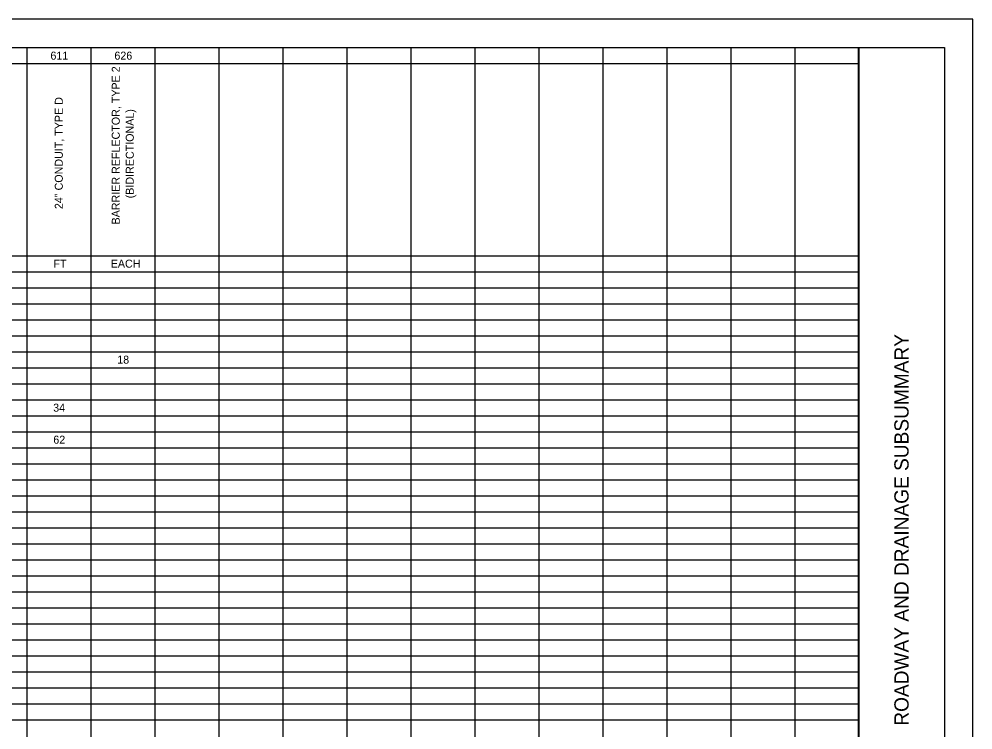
# Model space of a CAD drawing. Extents: x 0 to 34, y 0 to 22.
# Drawn here: x 17.31 to 34, y 9.56 to 22 of the extents above; entities that cross this region are included whole.
import ezdxf

# ---------------------------------------------------------------- set-up
doc = ezdxf.new("R2010")
doc.units = 0
for name, color, linetype in [('Default', 7, 'Continuous'), ('SH_Border', 7, 'Continuous'), ('SH_Cut_Line', 7, 'Continuous'), ('SH_Data', 7, 'Continuous')]:
    doc.layers.add(name, color=color, linetype=linetype)

msp = doc.modelspace()

# ---------------------------------------------------------------- linework, layer by layer
at = {"layer": 'SH_Border'}
msp.add_line((32, 0.5), (32, 21.5), dxfattribs=at)
msp.add_lwpolyline([(1.5, 21.5), (33.5, 21.5), (33.5, 0.5), (1.5, 0.5)], close=True, dxfattribs=at)
at = {"layer": 'SH_Cut_Line'}
msp.add_lwpolyline([(0, 0), (34, 0), (34, 22), (0, 22)], close=True, dxfattribs=at)
at = {"layer": 'SH_Data'}
for p, q in [((1.5, 21.5), (32.004, 21.5)), ((17.444, 21.5), (17.444, 0.5)), ((18.564, 21.5), (18.564, 0.5)), ((19.684, 21.5), (19.684, 0.5)), ((20.804, 21.5), (20.804, 0.5)), ((21.924, 21.5), (21.924, 0.5)), ((23.044, 21.5), (23.044, 0.5)), ((24.164, 21.5), (24.164, 0.5)), ((25.284, 21.5), (25.284, 0.5)), ((26.404, 21.5), (26.404, 0.5)), ((27.524, 21.5), (27.524, 0.5)), ((28.644, 21.5), (28.644, 0.5)), ((29.764, 21.5), (29.764, 0.5)), ((30.884, 21.5), (30.884, 0.5)), ((32.004, 21.5), (32.004, 0.5)), ((8.484, 21.22), (32.004, 21.22)), ((8.484, 17.86), (32.004, 17.86)), ((1.5, 17.58), (32.004, 17.58)), ((1.5, 17.3), (32.004, 17.3)), ((1.5, 17.02), (32.004, 17.02)), ((1.5, 16.74), (32.004, 16.74)), ((1.5, 16.46), (32.004, 16.46)), ((1.5, 16.18), (32.004, 16.18)), ((1.5, 15.9), (32.004, 15.9)), ((1.5, 15.62), (32.004, 15.62)), ((1.5, 15.34), (32.004, 15.34)), ((1.5, 15.06), (32.004, 15.06)), ((1.5, 14.78), (32.004, 14.78)), ((1.5, 14.5), (32.004, 14.5)), ((1.5, 14.22), (32.004, 14.22)), ((1.5, 13.94), (32.004, 13.94)), ((1.5, 13.66), (32.004, 13.66)), ((1.5, 13.38), (32.004, 13.38)), ((1.5, 13.1), (32.004, 13.1)), ((1.5, 12.82), (32.004, 12.82)), ((1.5, 12.54), (32.004, 12.54)), ((1.5, 12.26), (32.004, 12.26)), ((1.5, 11.98), (32.004, 11.98)), ((1.5, 11.7), (32.004, 11.7)), ((1.5, 11.42), (32.004, 11.42)), ((1.5, 11.14), (32.004, 11.14)), ((1.5, 10.86), (32.004, 10.86)), ((1.5, 10.58), (32.004, 10.58)), ((1.5, 10.3), (32.004, 10.3)), ((1.5, 10.02), (32.004, 10.02)), ((1.5, 9.74), (32.004, 9.74))]:
    msp.add_line(p, q, dxfattribs=at)

# ---------------------------------------------------------------- texts
at = {"layer": 'Default'}
for s, p in [('611', (17.858, 21.29)), ('626', (18.977, 21.29)), ('FT', (17.91, 17.65)), ('EACH', (18.913, 17.65)), ('18', (19.027, 15.97)), ('34', (17.906, 15.13)), ('62', (17.908, 14.57))]:
    msp.add_text(s, height=0.14, dxfattribs=at).set_placement(p)
for s, p in [('BARRIER REFLECTOR, TYPE 2 ', (19.071, 18.406)), ('24" CONDUIT, TYPE D', (18.074, 18.675)), ('(BIDIRECTIONAL)', (19.316, 18.864))]:
    msp.add_text(s, height=0.14, rotation=90, dxfattribs=at).set_placement(p)
at = {"layer": 'SH_Data'}
msp.add_text('ROADWAY AND DRAINAGE SUBSUMMARY', height=0.25, rotation=90, dxfattribs=at).set_placement((32.875, 9.635))

doc.saveas('drawing.dxf')
